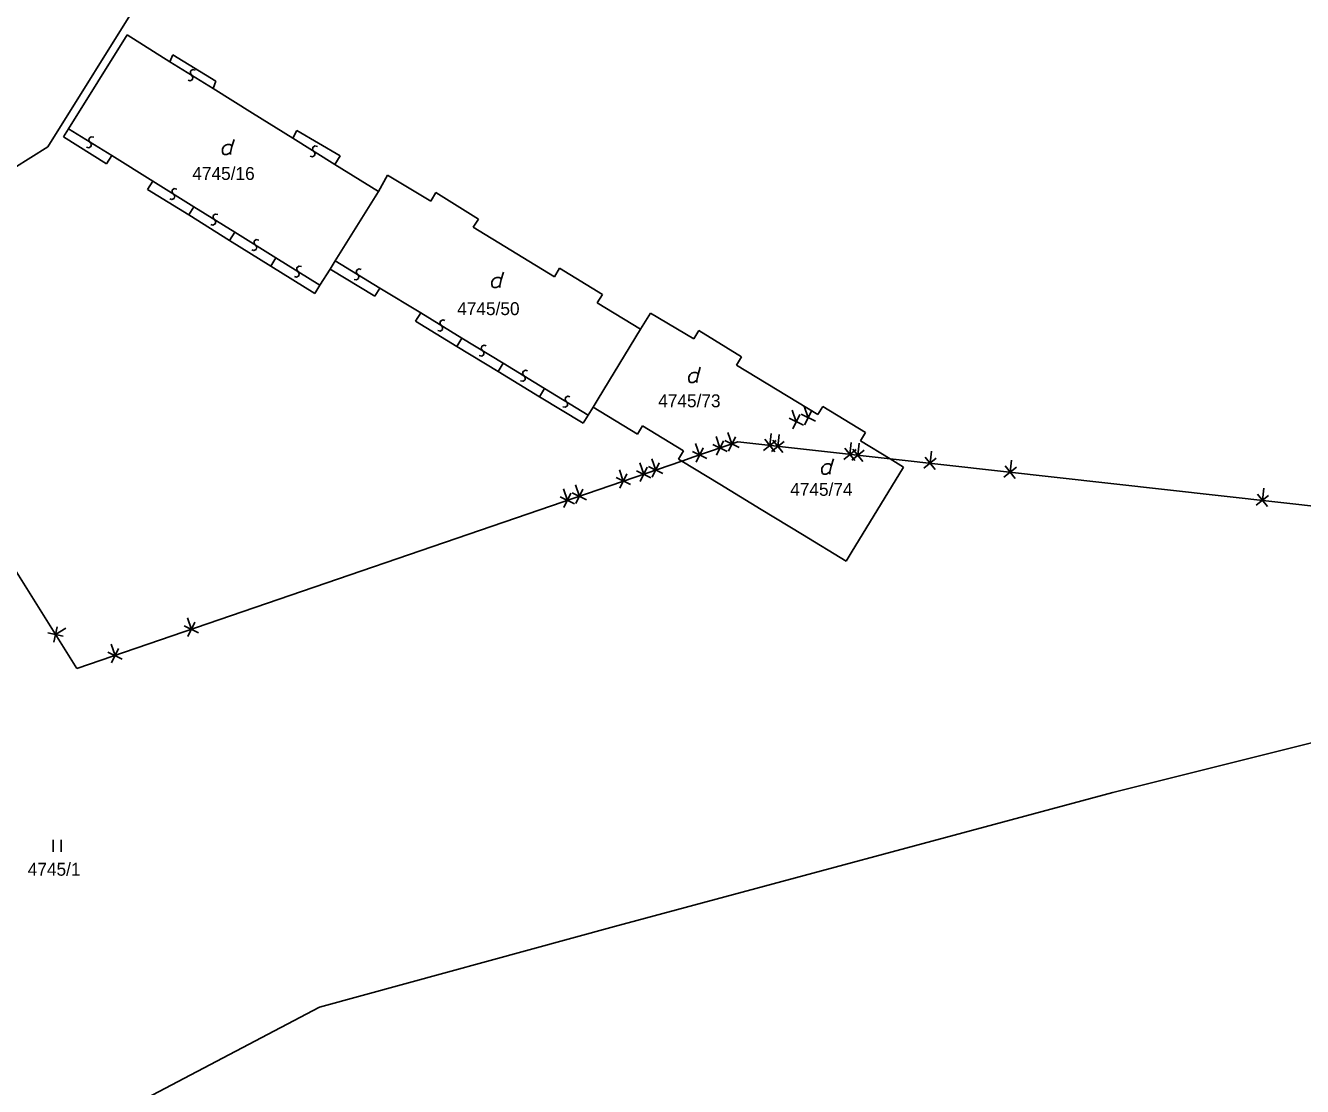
# Model space of a CAD drawing. Extents: x -266179 to -264727, y -1243225 to -1241702.
# Drawn here: x -265633.4 to -265475.1, y -1242285.7 to -1242154.1 of the extents above; entities that cross this region are included whole.
import ezdxf

# ---------------------------------------------------------------- set-up
doc = ezdxf.new("R2010")
doc.units = 0
for name, color, linetype in [('Vrstva 1', 7, 'Continuous'), ('Vrstva 2', 7, 'Continuous'), ('Vrstva 21', 7, 'Continuous')]:
    doc.layers.add(name, color=color, linetype=linetype)

msp = doc.modelspace()

# ---------------------------------------------------------------- linework, layer by layer
at = {"layer": 'Vrstva 1'}
for p, q in [((-265617.87, -1242148.59), (-265630.67, -1242169.12)), ((-265628.1, -1242166.89), (-265620.85, -1242155.25)), ((-265620.85, -1242155.25), (-265615.52, -1242158.57)), ((-265615.52, -1242158.57), (-265615.15, -1242157.72)), ((-265615.15, -1242157.72), (-265609.82, -1242160.98)), ((-265609.82, -1242160.98), (-265610.16, -1242161.91)), ((-265610.16, -1242161.91), (-265605.29, -1242164.95)), ((-265605.29, -1242164.95), (-265600.29, -1242168.06)), ((-265628.74, -1242167.91), (-265628.1, -1242166.89)), ((-265623.38, -1242171.24), (-265628.74, -1242167.91)), ((-265607.84, -1242169.11), (-265607.57, -1242168.21)), ((-265600.29, -1242168.06), (-265599.77, -1242167.09)), ((-265599.77, -1242167.09), (-265594.43, -1242170.27)), ((-265630.67, -1242169.12), (-265657.22, -1242185.77)), ((-265622.75, -1242170.22), (-265623.38, -1242171.24)), ((-265617.65, -1242173.4), (-265622.75, -1242170.22)), ((-265594.43, -1242170.27), (-265595.07, -1242171.31)), ((-265595.07, -1242171.31), (-265589.67, -1242174.67)), ((-265589.67, -1242174.67), (-265588.53, -1242172.64)), ((-265588.53, -1242172.64), (-265583.19, -1242175.89)), ((-265618.29, -1242174.42), (-265617.65, -1242173.4)), ((-265613.19, -1242177.59), (-265618.29, -1242174.42)), ((-265589.67, -1242174.67), (-265595.03, -1242183.28)), ((-265583.19, -1242175.89), (-265582.57, -1242174.81)), ((-265582.57, -1242174.81), (-265577.27, -1242178.09)), ((-265608.12, -1242180.75), (-265613.19, -1242177.59)), ((-265577.27, -1242178.09), (-265577.9, -1242179.12)), ((-265577.9, -1242179.12), (-265567.82, -1242185.26)), ((-265603.02, -1242183.93), (-265608.12, -1242180.75)), ((-265597.56, -1242187.33), (-265603.02, -1242183.93)), ((-265595.67, -1242184.3), (-265596.92, -1242186.31)), ((-265595.03, -1242183.28), (-265595.67, -1242184.3)), ((-265590.12, -1242187.68), (-265595.67, -1242184.3)), ((-265567.82, -1242185.26), (-265567.21, -1242184.17)), ((-265567.21, -1242184.17), (-265561.9, -1242187.46)), ((-265657.22, -1242185.77), (-265627.06, -1242233.87)), ((-265574.43, -1242185.6), (-265574.16, -1242184.7)), ((-265596.92, -1242186.31), (-265597.56, -1242187.33)), ((-265589.5, -1242186.66), (-265590.12, -1242187.68)), ((-265584.43, -1242189.74), (-265589.5, -1242186.66)), ((-265561.9, -1242187.46), (-265562.53, -1242188.48)), ((-265562.53, -1242188.48), (-265557.15, -1242191.76)), ((-265585.06, -1242190.76), (-265584.43, -1242189.74)), ((-265557.15, -1242191.76), (-265555.92, -1242189.76)), ((-265555.92, -1242189.76), (-265550.56, -1242192.96)), ((-265579.93, -1242193.89), (-265585.06, -1242190.76)), ((-265557.15, -1242191.76), (-265562.41, -1242200.39)), ((-265550.56, -1242192.96), (-265549.95, -1242191.93)), ((-265549.95, -1242191.93), (-265544.65, -1242195.17)), ((-265574.81, -1242197.01), (-265579.93, -1242193.89)), ((-265544.65, -1242195.17), (-265545.28, -1242196.2)), ((-265569.68, -1242200.13), (-265574.81, -1242197.01)), ((-265550.02, -1242197.38), (-265549.75, -1242196.48)), ((-265545.28, -1242196.2), (-265535.19, -1242202.36)), ((-265564.26, -1242203.43), (-265569.68, -1242200.13)), ((-265563.03, -1242201.42), (-265563.64, -1242202.41)), ((-265562.41, -1242200.39), (-265563.03, -1242201.42)), ((-265557.53, -1242204.77), (-265563.03, -1242201.42)), ((-265535.19, -1242202.36), (-265534.56, -1242201.34)), ((-265534.56, -1242201.34), (-265529.26, -1242204.58)), ((-265563.64, -1242202.41), (-265564.26, -1242203.43)), ((-265556.9, -1242203.75), (-265557.53, -1242204.77)), ((-265551.82, -1242206.85), (-265556.9, -1242203.75)), ((-265529.26, -1242204.58), (-265529.88, -1242205.6)), ((-265550.56, -1242207.61), (-265545.11, -1242205.74)), ((-265545.11, -1242205.74), (-265526.22, -1242207.84)), ((-265529.88, -1242205.6), (-265526.22, -1242207.84)), ((-265552.44, -1242207.87), (-265551.82, -1242206.85)), ((-265552.04, -1242208.12), (-265552.44, -1242207.87)), ((-265552.04, -1242208.12), (-265550.56, -1242207.61)), ((-265533.51, -1242208.74), (-265533.24, -1242207.84)), ((-265524.54, -1242208.87), (-265526.22, -1242207.84)), ((-265526.22, -1242207.84), (-265465.13, -1242214.65)), ((-265627.06, -1242233.87), (-265552.04, -1242208.12)), ((-265552.04, -1242208.12), (-265547.32, -1242210.99)), ((-265531.03, -1242219.52), (-265524.54, -1242208.87)), ((-265547.32, -1242210.99), (-265542.2, -1242214.11)), ((-265542.2, -1242214.11), (-265537.07, -1242217.24)), ((-265537.07, -1242217.24), (-265531.65, -1242220.54)), ((-265531.65, -1242220.54), (-265531.03, -1242219.52)), ((-265435.54, -1242233.42), (-265498.59, -1242249.25)), ((-265498.59, -1242249.25), (-265560.39, -1242265.86)), ((-265630.01, -1242255.1), (-265630.01, -1242256.6)), ((-265629.01, -1242256.6), (-265629.01, -1242255.1)), ((-265560.39, -1242265.86), (-265596.98, -1242275.85)), ((-265596.98, -1242275.85), (-265629.09, -1242292.75))]:
    msp.add_line(p, q, dxfattribs=at)
for points in [[(-265608.02, -1242170.1), (-265608.02, -1242169.83), (-265607.84, -1242169.11), (-265607.93, -1242168.93), (-265608.11, -1242168.84), (-265608.38, -1242168.84), (-265608.65, -1242168.93), (-265608.83, -1242169.11), (-265609.01, -1242169.38), (-265609.01, -1242169.74), (-265608.92, -1242170.01), (-265608.74, -1242170.1), (-265608.47, -1242170.1), (-265608.29, -1242170.01), (-265608.02, -1242169.83)], [(-265574.61, -1242186.59), (-265574.61, -1242186.32), (-265574.43, -1242185.6), (-265574.52, -1242185.42), (-265574.7, -1242185.33), (-265574.97, -1242185.33), (-265575.24, -1242185.42), (-265575.42, -1242185.6), (-265575.6, -1242185.87), (-265575.6, -1242186.23), (-265575.51, -1242186.5), (-265575.33, -1242186.59), (-265575.06, -1242186.59), (-265574.88, -1242186.5), (-265574.61, -1242186.32)], [(-265550.2, -1242198.37), (-265550.2, -1242198.1), (-265550.02, -1242197.38), (-265550.11, -1242197.2), (-265550.29, -1242197.11), (-265550.56, -1242197.11), (-265550.83, -1242197.2), (-265551.01, -1242197.38), (-265551.19, -1242197.65), (-265551.19, -1242198.01), (-265551.1, -1242198.28), (-265550.92, -1242198.37), (-265550.65, -1242198.37), (-265550.47, -1242198.28), (-265550.2, -1242198.1)], [(-265533.69, -1242209.73), (-265533.69, -1242209.46), (-265533.51, -1242208.74), (-265533.6, -1242208.56), (-265533.78, -1242208.47), (-265534.05, -1242208.47), (-265534.32, -1242208.56), (-265534.5, -1242208.74), (-265534.68, -1242209.01), (-265534.68, -1242209.37), (-265534.59, -1242209.64), (-265534.41, -1242209.73), (-265534.14, -1242209.73), (-265533.96, -1242209.64), (-265533.69, -1242209.46)]]:
    msp.add_lwpolyline(points, dxfattribs=at)
at = {"layer": 'Vrstva 2'}
for p, q in [((-265615.52, -1242158.57), (-265610.16, -1242161.91)), ((-265628.1, -1242166.89), (-265622.75, -1242170.22)), ((-265600.29, -1242168.06), (-265595.07, -1242171.31)), ((-265617.65, -1242173.4), (-265612.56, -1242176.57)), ((-265612.56, -1242176.57), (-265613.19, -1242177.59)), ((-265612.56, -1242176.57), (-265607.48, -1242179.73)), ((-265607.48, -1242179.73), (-265608.12, -1242180.75)), ((-265607.48, -1242179.73), (-265602.39, -1242182.91)), ((-265602.39, -1242182.91), (-265603.02, -1242183.93)), ((-265602.39, -1242182.91), (-265596.92, -1242186.31)), ((-265589.5, -1242186.66), (-265595.03, -1242183.28)), ((-265579.31, -1242192.86), (-265584.43, -1242189.74)), ((-265579.93, -1242193.89), (-265579.31, -1242192.86)), ((-265574.18, -1242195.98), (-265579.31, -1242192.86)), ((-265574.81, -1242197.01), (-265574.18, -1242195.98)), ((-265569.06, -1242199.1), (-265574.18, -1242195.98)), ((-265569.68, -1242200.13), (-265569.06, -1242199.1)), ((-265563.64, -1242202.41), (-265569.06, -1242199.1))]:
    msp.add_line(p, q, dxfattribs=at)
for points in [[(-265612.401, -1242159.63), (-265612.722, -1242159.559), (-265612.974, -1242159.756), (-265612.988, -1242160.042), (-265612.669, -1242160.476), (-265612.743, -1242160.784), (-265613.021, -1242160.928), (-265613.279, -1242160.85)], [(-265624.986, -1242167.945), (-265625.307, -1242167.874), (-265625.559, -1242168.071), (-265625.573, -1242168.357), (-265625.254, -1242168.791), (-265625.328, -1242169.099), (-265625.606, -1242169.243), (-265625.864, -1242169.165)], [(-265597.241, -1242169.075), (-265597.562, -1242169.004), (-265597.814, -1242169.201), (-265597.828, -1242169.487), (-265597.509, -1242169.921), (-265597.583, -1242170.229), (-265597.861, -1242170.373), (-265598.119, -1242170.295)], [(-265614.666, -1242174.375), (-265614.987, -1242174.304), (-265615.239, -1242174.501), (-265615.253, -1242174.787), (-265614.934, -1242175.221), (-265615.008, -1242175.529), (-265615.286, -1242175.673), (-265615.544, -1242175.595)], [(-265609.582, -1242177.539), (-265609.903, -1242177.469), (-265610.155, -1242177.666), (-265610.168, -1242177.952), (-265609.849, -1242178.386), (-265609.922, -1242178.694), (-265610.201, -1242178.838), (-265610.458, -1242178.761)], [(-265604.495, -1242180.71), (-265604.817, -1242180.639), (-265605.069, -1242180.836), (-265605.082, -1242181.122), (-265604.764, -1242181.556), (-265604.838, -1242181.864), (-265605.117, -1242182.008), (-265605.375, -1242181.93)], [(-265599.217, -1242183.999), (-265599.538, -1242183.929), (-265599.79, -1242184.126), (-265599.803, -1242184.412), (-265599.484, -1242184.846), (-265599.557, -1242185.154), (-265599.836, -1242185.298), (-265600.093, -1242185.221)], [(-265592.699, -1242185.584), (-265592.377, -1242185.652), (-265592.127, -1242185.453), (-265592.116, -1242185.167), (-265592.438, -1242184.735), (-265592.367, -1242184.427), (-265592.09, -1242184.28), (-265591.831, -1242184.356)], [(-265582.303, -1242191.914), (-265581.981, -1242191.982), (-265581.731, -1242191.783), (-265581.72, -1242191.497), (-265582.043, -1242191.066), (-265581.972, -1242190.757), (-265581.695, -1242190.61), (-265581.437, -1242190.686)], [(-265577.178, -1242195.035), (-265576.856, -1242195.102), (-265576.606, -1242194.903), (-265576.595, -1242194.616), (-265576.918, -1242194.186), (-265576.848, -1242193.877), (-265576.571, -1242193.73), (-265576.312, -1242193.805)], [(-265572.053, -1242198.154), (-265571.731, -1242198.222), (-265571.481, -1242198.023), (-265571.47, -1242197.737), (-265571.793, -1242197.306), (-265571.722, -1242196.997), (-265571.445, -1242196.85), (-265571.187, -1242196.926)], [(-265566.784, -1242201.369), (-265566.462, -1242201.437), (-265566.212, -1242201.238), (-265566.201, -1242200.952), (-265566.523, -1242200.52), (-265566.452, -1242200.212), (-265566.175, -1242200.065), (-265565.916, -1242200.141)]]:
    msp.add_lwpolyline(points, dxfattribs=at)
at = {"layer": 'Vrstva 21'}
for p, q in [((-265657.22, -1242185.77), (-265627.06, -1242233.87)), ((-265627.06, -1242233.87), (-265657.22, -1242185.77)), ((-265536.372, -1242202.742), (-265536.858, -1242201.324)), ((-265536.968, -1242203.669), (-265538.747, -1242202.801)), ((-265537.858, -1242203.235), (-265538.346, -1242201.817)), ((-265538.292, -1242204.125), (-265537.424, -1242202.346)), ((-265535.483, -1242203.177), (-265537.261, -1242202.307)), ((-265536.807, -1242203.632), (-265535.937, -1242201.853)), ((-265545.831, -1242205.987), (-265546.317, -1242204.568)), ((-265541.128, -1242206.183), (-265540.963, -1242204.692)), ((-265540.141, -1242206.293), (-265539.975, -1242204.802)), ((-265550.56, -1242207.61), (-265545.11, -1242205.74)), ((-265545.11, -1242205.74), (-265550.56, -1242207.61)), ((-265549.839, -1242207.363), (-265550.326, -1242205.944)), ((-265550.274, -1242208.253), (-265549.404, -1242206.474)), ((-265546.424, -1242206.923), (-265548.203, -1242206.055)), ((-265547.314, -1242206.489), (-265547.802, -1242205.071)), ((-265547.748, -1242207.379), (-265546.879, -1242205.599)), ((-265544.942, -1242206.422), (-265546.72, -1242205.552)), ((-265546.266, -1242206.876), (-265545.396, -1242205.097)), ((-265545.11, -1242205.74), (-265526.22, -1242207.84)), ((-265526.22, -1242207.84), (-265545.11, -1242205.74)), ((-265541.901, -1242206.802), (-265540.355, -1242205.565)), ((-265540.51, -1242206.956), (-265541.747, -1242205.41)), ((-265540.914, -1242206.912), (-265539.368, -1242205.675)), ((-265539.522, -1242207.066), (-265540.759, -1242205.52)), ((-265530.571, -1242208.06), (-265531.808, -1242206.514)), ((-265531.189, -1242207.287), (-265531.024, -1242205.796)), ((-265530.202, -1242207.397), (-265530.036, -1242205.906)), ((-265555.286, -1242209.241), (-265555.775, -1242207.823)), ((-265552.04, -1242208.12), (-265550.56, -1242207.61)), ((-265550.56, -1242207.61), (-265552.04, -1242208.12)), ((-265548.95, -1242207.798), (-265550.728, -1242206.928)), ((-265531.962, -1242207.905), (-265530.416, -1242206.668)), ((-265530.975, -1242208.015), (-265529.429, -1242206.778)), ((-265529.583, -1242208.17), (-265530.82, -1242206.624)), ((-265526.22, -1242207.84), (-265465.13, -1242214.65)), ((-265465.13, -1242214.65), (-265526.22, -1242207.84)), ((-265522.024, -1242209.015), (-265520.478, -1242207.778)), ((-265520.633, -1242209.169), (-265521.869, -1242207.623)), ((-265521.251, -1242208.396), (-265521.085, -1242206.905)), ((-265511.312, -1242209.5), (-265511.147, -1242208.009)), ((-265627.06, -1242233.87), (-265552.04, -1242208.12)), ((-265552.04, -1242208.12), (-265627.06, -1242233.87)), ((-265559.298, -1242210.608), (-265559.785, -1242209.189)), ((-265555.88, -1242210.179), (-265557.658, -1242209.309)), ((-265556.769, -1242209.744), (-265557.255, -1242208.325)), ((-265557.204, -1242210.634), (-265556.334, -1242208.855)), ((-265554.397, -1242209.675), (-265556.176, -1242208.807)), ((-265555.721, -1242210.131), (-265554.852, -1242208.351)), ((-265512.085, -1242210.118), (-265510.539, -1242208.881)), ((-265510.694, -1242210.273), (-265511.931, -1242208.727)), ((-265564.742, -1242212.495), (-265565.23, -1242211.076)), ((-265558.409, -1242211.043), (-265560.187, -1242210.173)), ((-265559.733, -1242211.497), (-265558.863, -1242209.718)), ((-265565.339, -1242213.424), (-265567.117, -1242212.554)), ((-265566.228, -1242212.989), (-265566.715, -1242211.57)), ((-265566.663, -1242213.878), (-265565.793, -1242212.099)), ((-265563.853, -1242212.929), (-265565.632, -1242212.061)), ((-265565.176, -1242213.384), (-265564.308, -1242211.605)), ((-265480.811, -1242213.609), (-265479.265, -1242212.372)), ((-265479.419, -1242213.763), (-265480.656, -1242212.217)), ((-265480.038, -1242212.99), (-265479.872, -1242211.499)), ((-265629.937, -1242230.598), (-265629.494, -1242228.669)), ((-265611.983, -1242229.436), (-265613.761, -1242228.566)), ((-265612.872, -1242229.001), (-265613.359, -1242227.582)), ((-265613.307, -1242229.891), (-265612.437, -1242228.112)), ((-265630.68, -1242229.412), (-265628.751, -1242229.855)), ((-265629.716, -1242229.633), (-265628.445, -1242228.836)), ((-265621.442, -1242232.681), (-265623.22, -1242231.811)), ((-265622.331, -1242232.246), (-265622.818, -1242230.827)), ((-265622.766, -1242233.135), (-265621.896, -1242231.356))]:
    msp.add_line(p, q, dxfattribs=at)

# ---------------------------------------------------------------- texts
at = {"layer": 'Vrstva 1'}
for s, p in [('4745/16', (-265612.752, -1242173.24)), ('4745/50', (-265579.9, -1242190.01)), ('4745/73', (-265554.971, -1242201.44)), ('4745/74', (-265538.601, -1242212.43)), ('4745/1', (-265633.164, -1242259.56))]:
    msp.add_text(s, height=1.6, dxfattribs=at).set_placement(p)

doc.saveas('drawing.dxf')
